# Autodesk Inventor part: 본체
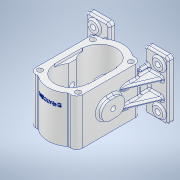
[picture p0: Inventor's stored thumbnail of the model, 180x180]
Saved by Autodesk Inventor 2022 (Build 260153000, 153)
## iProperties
Created: 2023-06
Part Number: 본체
Material: 알루미늄 6061
Document SubType Name: Modeling
Designer: PC-03
Density: 2.7 g/cm^3
Appearance: 알루미늄 - 평지
Mass: 1176.69 g
Surface Area: 976.867 cm^2
Volume: 435.809 cm^3
Author: PC-03
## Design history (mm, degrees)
sketch "스케치4"
  geometry: L1 (-70, 50)-(-30, 50); L2 (-30, 50)-(-30, -50); L3 (-30, -50)-(-70, -50); L4 (-70, -50)-(-70, 50); L5 (-70, 50)-(-30, -50); L6 (-30, 50)-(-70, -50); L7 (30, 50)-(70, 50); L8 (70, 50)-(70, -50); L9 (70, -50)-(30, -50); L10 (30, -50)-(30, 50); L11 (30, 50)-(70, -50); L12 (70, 50)-(30, -50); L13 (-98, 0)-(98, 0) reference; L14 (0, -70)-(0, 70) reference; 3 further points
  constraints: 24 end point, 4 midpoint, 4 parallel, 3 symmetric about line, 2 horizontal, 2 perpendicular, 1 point on line
  dimensions: "d16" = 40 distance of L1.start L1.end; "d17" = 100 distance of L3.end L1.start; "d18" = 140 distance between parallel lines of L8 L4
extrude "돌출3" new body sketch "스케치4" distance "d19" = 9; taper "d20" = 0 deg
sketch "스케치5"
  geometry: L1 (-98, 0)-(98, 0) reference; L2 (-55, 83)-(-55, -67.41); L3 (0, -106.516)-(0, 114.586) reference; L4 (55, 81.496)-(55, -74.93); C1 r 9 at (-55, 35); C2 r 9 at (-55, -35); C3 r 9 at (55, 35); C4 r 9 at (55, -35); 1 further point
  constraints: 4 centre point, 4 end point, 2 point on line, 2 symmetric about line, 2 vertical, 1 other
  dimensions: "d21" = 18 diameter of C1; "d23" = 110 distance between parallel lines of L4 L2; "d24" = 70 distance of C2.centre C1.centre; "d25" = 70 distance of C4.centre C3.centre; "d26" = 18 diameter of C2; "d27" = 18 diameter of C4; "d28" = 18 diameter of C3
extrude "돌출4" join sketch "스케치5" distance "d29" = 3; taper "d30" = 0 deg
sketch "스케치6"
  geometry: C1 r 4.5 at (0, 0); C2 r 9 at (0, 0) reference; 1 further point
  constraints: 1 centre point, 1 coincident
  dimensions: "d31" = 9 diameter of C1
extrude "돌출5" cut sketch "스케치6" extent not by distance; stored distance "d32" = 50; taper "d33" = 0 deg
sketch "스케치7"
  geometry: L1 (0, 129.709)-(0, 30.291); L2 (0, -28.8)-(0, 172.8) reference; L3 (73.621, 80)-(-78.887, 80); L4 (-30, 0)-(-70, 0) reference; L5 (40, 135)-(-40, 135); L6 (-40, 135)-(-40, 25); L7 (-40, 25)-(40, 25); L8 (40, 25)-(40, 135); L9 (40, 135)-(-40, 25); L10 (-40, 135)-(40, 25); C1 r 40 at (0, 104); C2 r 40 at (0, 56); 6 further points
  constraints: 18 end point, 4 point on line, 3 midpoint, 2 centre point, 2 horizontal, 2 parallel, 1 perpendicular, 1 symmetric about line, 1 tangent, 1 vertical
  dimensions: "d34" = 80 distance between parallel lines of L4 L3; "d36" = 80 diameter of C2; "d37" = 80 diameter of C1; "d38" = 48 distance of C2.centre C1.centre; "d39" = 110 distance of L5.end L6.end
extrude "돌출6" join sketch "스케치7" stored distance "d40" = 79; taper "d41" = 0 deg
sketch "스케치9"
  geometry: L1 (-30, -50)-(-30, 50) reference; L2 (-38, 25)-(-30, 25); L3 (-30, 25)-(-30, -25); L4 (-30, -25)-(-38, -25); L5 (-38, -25)-(-38, 25); L6 (-98, 0)-(98, 0) reference; 1 further point
  constraints: 8 end point, 2 parallel, 1 horizontal, 1 perpendicular, 1 point on line, 1 other
  dimensions: "d45" = 50 distance of L4.end L2.start; "d46" = 8 distance of L2.start L2.end
extrude "돌출7" join sketch "스케치9" stored distance "d47" = 40; taper "d48" = 0 deg
sketch "스케치10"
  geometry: L1 (62, 9)-(40, 60.829); L2 (40, 25)-(40, 135) reference; L3 (70, 0)-(70, 9) reference; L4 (30, 9)-(70, 9) reference; 3 further points
  constraints: 2 end point, 2 point on line
  dimensions: "d49" = 23 deg angle of L3 L1; "d50" = 8 distance from line of L3 L1.start
feature "리브1" sketch "스케치10" dims "d51" = 1, "d52" = 36, "d53" = 0, "d54" = 0, "d55" = 1, "d56" = 1
sketch "스케치11"
  geometry: L1 (40, 25)-(40, 60.829) reference; L2 (38, 25)-(40, 25) reference; L3 (38, 9)-(38, 25) reference; L4 (62, 9)-(38, 9) reference; L5 (40, 60.829)-(62, 9) reference; L6 (62, 9)-(40, 60.829); L7 (40, 25)-(40, 135) reference; L8 (40, 60.829)-(40, 25); L9 (38, 25)-(40, 25) reference; L10 (40, 25)-(38, 25); L11 (38, 9)-(38, 25) reference; L12 (38, 25)-(38, 9); L13 (38, 9)-(62, 9); 1 further point
  constraints: 10 end point, 2 collinear, 2 perpendicular
extrude "돌출8" cut sketch "스케치11" stored distance "d57" = 22; taper "d58" = 0 deg
sketch "스케치12"
  geometry: L1 (0, 85)-(0, 75); L2 (15, 85)-(15, 75); L3 (-15, 75)-(-15, 85); L4 (0, -28.8)-(0, 172.8) reference; L5 (50, 0)-(-50, 0) reference; A1 r 15 centre (0, 85) between (15, 85) and (-15, 85); A2 r 15 centre (0, 75) between (-15, 75) and (15, 75); 2 further points
  constraints: 8 end point, 4 point on circle, 4 tangent, 2 centre point, 1 midpoint, 1 parallel, 1 point on line, 1 vertical
  dimensions: "d59" = 30 distance between parallel lines of L3 L2; "d60" = 80 distance from line of L5 point (0, 80); "d61" = 10 distance of L1.start L1.end
extrude "돌출9" join sketch "스케치12" stored distance "d62" = 95; taper "d63" = 0 deg
sketch "스케치14" dims "d68" = 57
  geometry: L1 (0, 28.8)-(0, -172.8) reference; L2 (62.711, -80)-(-77.674, -80); L3 (-30, 0)-(-70, 0) reference; L4 (22.5, -86.507)-(-22.5, -86.507); L5 (-22.5, -86.507)-(-22.5, -73.493); L6 (-22.5, -73.493)-(22.5, -73.493); L7 (22.5, -73.493)-(22.5, -86.507); L8 (22.5, -86.507)-(-22.5, -73.493); L9 (-22.5, -86.507)-(22.5, -73.493); C1 r 28.5 at (0, -104); 6 further points
  constraints: 14 end point, 4 point on line, 2 horizontal, 2 midpoint, 2 parallel, 1 centre point, 1 perpendicular, 1 symmetric about line, 3 other
  dimensions: "d65" = 80 distance between parallel lines of L3 L2; "d66" = 48 distance of point (0, -56) C1.centre; "d67" = 57 diameter of C1; "d69" = 45 distance of L4.start L4.end
extrude "돌출10" cut sketch "스케치14" extent not by distance; stored distance "d70" = 0; taper "d71" = 0 deg
sketch "스케치15"
  geometry: L1 (29.5, -104)-(22.5, -104); L2 (22.5, -104)-(22.5, -56); L3 (22.5, -56)-(29.5, -56); L4 (29.5, -56)-(29.5, -104); L5 (67.864, -80)-(-92.433, -80); L6 (-30, 0)-(-70, 0) reference; 2 further points
  constraints: 10 end point, 2 horizontal, 2 parallel, 1 perpendicular, 1 point on line, 1 other
  dimensions: "d72" = 80 distance between parallel lines of L6 L5; "d73" = 48 distance of L1.end L2.end; "d74" = 7 distance of L1.start L1.end
extrude "돌출11" cut sketch "스케치15" distance "d75" = 4.5; taper "d76" = 0 deg
sketch "스케치16"
  geometry: L1 (89.655, -80)-(-117.61, -80); L2 (-30, 0)-(-70, 0) reference; L3 (0, 28.8)-(0, -172.8) reference; C1 r 4.5 at (32.5, -125); C2 r 4.5 at (-32.5, -125); C3 r 4.5 at (32.5, -35); C4 r 4.5 at (-32.5, -35); 1 further point
  constraints: 4 centre point, 3 symmetric about line, 2 end point, 1 horizontal
  dimensions: "d77" = 80 distance between parallel lines of L2 L1; "d78" = 65 distance of C2.centre C1.centre; "d79" = 90 distance of C3.centre C1.centre; "d80" = 9 diameter of C1; "d81" = 9 diameter of C2; "d82" = 9 diameter of C4; "d83" = 9 diameter of C3
extrude "돌출12" cut sketch "스케치16" extent not by distance; stored distance "d84" = 0; taper "d85" = 0 deg
sketch "스케치17"
  geometry: L1 (80, 84.854)-(80, -90.502); L2 (0, 50)-(0, -50) reference; L3 (-28.8, 0)-(172.8, 0) reference; 2 further points
  constraints: 2 end point, 2 point on line, 1 vertical
  dimensions: "d86" = 80 distance between parallel lines of L2 L1
hole "구멍1" sketch "스케치17" at (80, 0) diameter "d87" = 8.376; stored, may be unused: countersink angle "d91" = 90 deg, drill point angle "d93" = 0 deg; dims "d88" = 10, "d89" = 4, "d90" = 2, "d92" = 27.3
fillet "모깎기1" dims "d94" = 5
fillet "모깎기2" dims "d95" = 10
fillet "모깎기4" dims "d97" = 3
fillet "모깎기5" dims "d98" = 3
fillet "모깎기7" dims "d100" = 3
fillet "모깎기8" dims "d101" = 3
fillet "모깎기9" dims "d102" = 3
sketch "스케치19"
  geometry: C1 r 4.5 at (0, 0); C2 r 4.5 at (0, 0) reference; 1 further point
  constraints: 1 centre point, 1 coincident
  dimensions: "d104" = 9 diameter of C1
extrude "돌출13" cut sketch "스케치19" extent not by distance; stored distance "d105" = 0; taper "d106" = 0 deg
node "작업 평면1"
sketch "스케치20"
  geometry: L1 (0, -70)-(0, 70) reference; L2 (-98, 0)-(98, 0) reference; 2 further points
  constraints: 1 point on line, 1 other
  dimensions: "d108" = 20 distance from line of L2 point (0, 20)
feature "엠보싱1" sketch "스케치20" dims "d16" = 40, "d17" = 100, "d18" = 140, "d21" = 18, "d23" = 110, "d24" = 70, "d25" = 70, "d26" = 18, "d27" = 18, "d28" = 18, "d109" = 0.5, "d110" = 0
node "솔리드2"
mirror "미러1"
mirror "미러2"
mirror "미러3"
mirror "미러4"
mirror "미러5"
mirror "미러6"
mirror "미러7"
node "투영된 루프1"
node "투영된 루프2"
node "투영된 루프3"
feature "A9D066F2-1C7D-4E18-AEED-F7BC21143FA4" dims "d87" = 8.376, "d88" = 10, "d89" = 4, "d90" = 2, "d91" = 90 deg, "d92" = 27.3, "d93" = 0
other parameters: "d107" = 144
